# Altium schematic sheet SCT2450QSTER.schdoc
size 127 x 101 mm
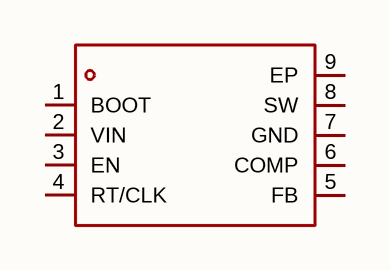
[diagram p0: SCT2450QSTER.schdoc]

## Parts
U?  sct2450qster  [ESOP-8_L4.9-W3.9-P1.27-LS6.0-BL-EP]  (value not drawn)

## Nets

Not connected (* = marked no-connect by the designer): U? 1(BOOT) 2(VIN) 3(EN) 4(RT/CLK) 5(FB) 6(COMP) 7(GND) 8(SW) 9(EP)

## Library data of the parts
U? = sct2450qster: 功能类型:降压型;工作电压:3.8V~36V;输出电压:800mV~36V;输出电流:5A;输出类型:可调;; Manufacturer: SCT(芯洲科技); AddInBom: yes; ModelId: d3e00daa36c445139c055a3b9efb85d2; ModelName: ESOP-8_L4.9-W3.9-H1.6-LS6.0-P1.27; ModelTransform: 240.157,192.913,0,90,0,0,0,0,0; Function: 降压型; Output Current: 5A; Frequency - Switching: 100kHz~2.2MHz; Synchronous Rectifier: 是; Number of Outputs: 1; Topology: 降压式; Quiescent Current: 25uA; Switch tube (built-in/external): 内置; Output Type: 可调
